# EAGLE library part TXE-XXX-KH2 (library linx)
KH2 SERIES TRANSMITTER / ENCODER Source: http://www.linxtechnologies.com .. TXE-xxx-KH2_Data_Guide.pdf
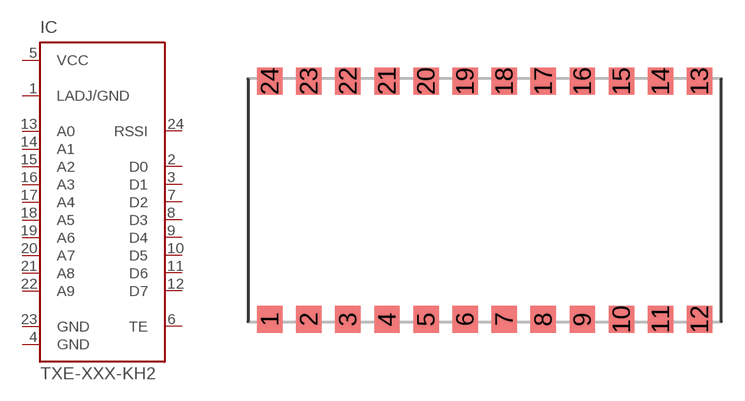
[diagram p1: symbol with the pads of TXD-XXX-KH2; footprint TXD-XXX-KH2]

Designator prefix IC

## TXE-XXX-KH2  [TXD-XXX-KH2]
1  LADJ/GND  in
2  D0  in
3  D1  in
4  GND  pwr
5  VCC  pwr
6  TE  in
7  D2  in
8  D3  in
9  D4  in
10  D5  in
11  D6  in
12  D7  in
13  A0  in
14  A1  in
15  A2  in
16  A3  in
17  A4  in
18  A5  in
19  A6  in
20  A7  in
21  A8  in
22  A9  in
23  GND  pwr
24  RSSI  in

## Footprint TXD-XXX-KH2 (pad centres in mm)
TXD-xxx-KH2 Source: All Packages.pdf
smd 1.651 x 1.778: 1 -13.97,-7.747; 2 -11.43,-7.747; 3 -8.89,-7.747; 4 -6.35,-7.747; 5 -3.81,-7.747; 6 -1.27,-7.747; 7 1.27,-7.747; 8 3.81,-7.747; 9 6.35,-7.747; 10 8.89,-7.747; 11 11.43,-7.747; 12 13.97,-7.747; 13 13.97,7.747; 14 11.43,7.747; 15 8.89,7.747; 16 6.35,7.747; 17 3.81,7.747; 18 1.27,7.747; 19 -1.27,7.747; 20 -3.81,7.747; 21 -6.35,7.747; 22 -8.89,7.747; 23 -11.43,7.747; 24 -13.97,7.747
